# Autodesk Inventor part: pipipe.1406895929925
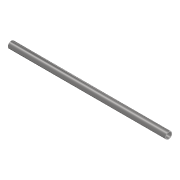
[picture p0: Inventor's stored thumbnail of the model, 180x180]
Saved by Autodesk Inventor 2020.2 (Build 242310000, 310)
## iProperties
Manager: www.cadconsulting.pl
Company: Fabian Stasiak CAD Consulting
IsCustomPart: 1
NAME: PIPING: JIS G 3458 Pipe
DATA: <meta><inlinegroups number="1" deflen="10"></inlinegroups><connections number="2"></connections><angles><a>3.14159265358979</a></angles></meta>
Created: 2014-08
Material: Stal, stopowa
Description: Rura
Document SubType Name: Modeling
Standard: JIS G 3458
Designer: F.Stasiak
Standards Organization: JIS
Language: pl-PL
Size Designation: 40 A x Sch 80 - 100
Categories: <MemberInstance><Categories><Category DisplayName="Rury cienko- i grubościenne" InternalName="4347fa0f-2144-441d-94cd-e3e15c92b736" Mnemonic="TUBEANDPIPE"><Cate
Stock Number: JIS G 3458 Rura 40 A x Sch 80
Density: 7.73 g/cm^3
Appearance: Częściowo polerowana
Catalog Web Link: www.expertbooks.pl
L: 1136,000 mm
PL: 1136,000 mm
Author: F.Stasiak
Subject: Zbiór ćwiczeń. Autodesk Inventor 2020. Kurs Professional
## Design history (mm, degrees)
sketch "Sketch1"
  geometry: C1 r 24.3 at (0, 0); C2 r 19.2 at (0, 0); 1 further point
  constraints: 2 centre point, 2 coincident, 1 concentric
  dimensions: "d0" = 48.6 diameter of C1 (= OD); "d1" = 38.4 diameter of C2 (= OD - 2 x t)
extrude "Extrusion1" new body sketch "Sketch1" distance "d2" = 1136 (= L); taper "d3" = 0 deg
workaxis "Work Axis1"
workpoint "Work Point1"
workaxis "Work Axis2"
workpoint "Work Point2"
body "Solid1"
other parameters: "OD" = 48.6 [user parameter; used in 2 equation terms], "t" = 5.1 [user parameter; used in 1 equation term], "L" = 1136 (= PL) [user parameter; used in 1 equation term], "ID" = 38.4 [user parameter], "PL" = 1136 [user parameter; used in 1 equation term], "Size_Designation" = 12.345 [user parameter]
